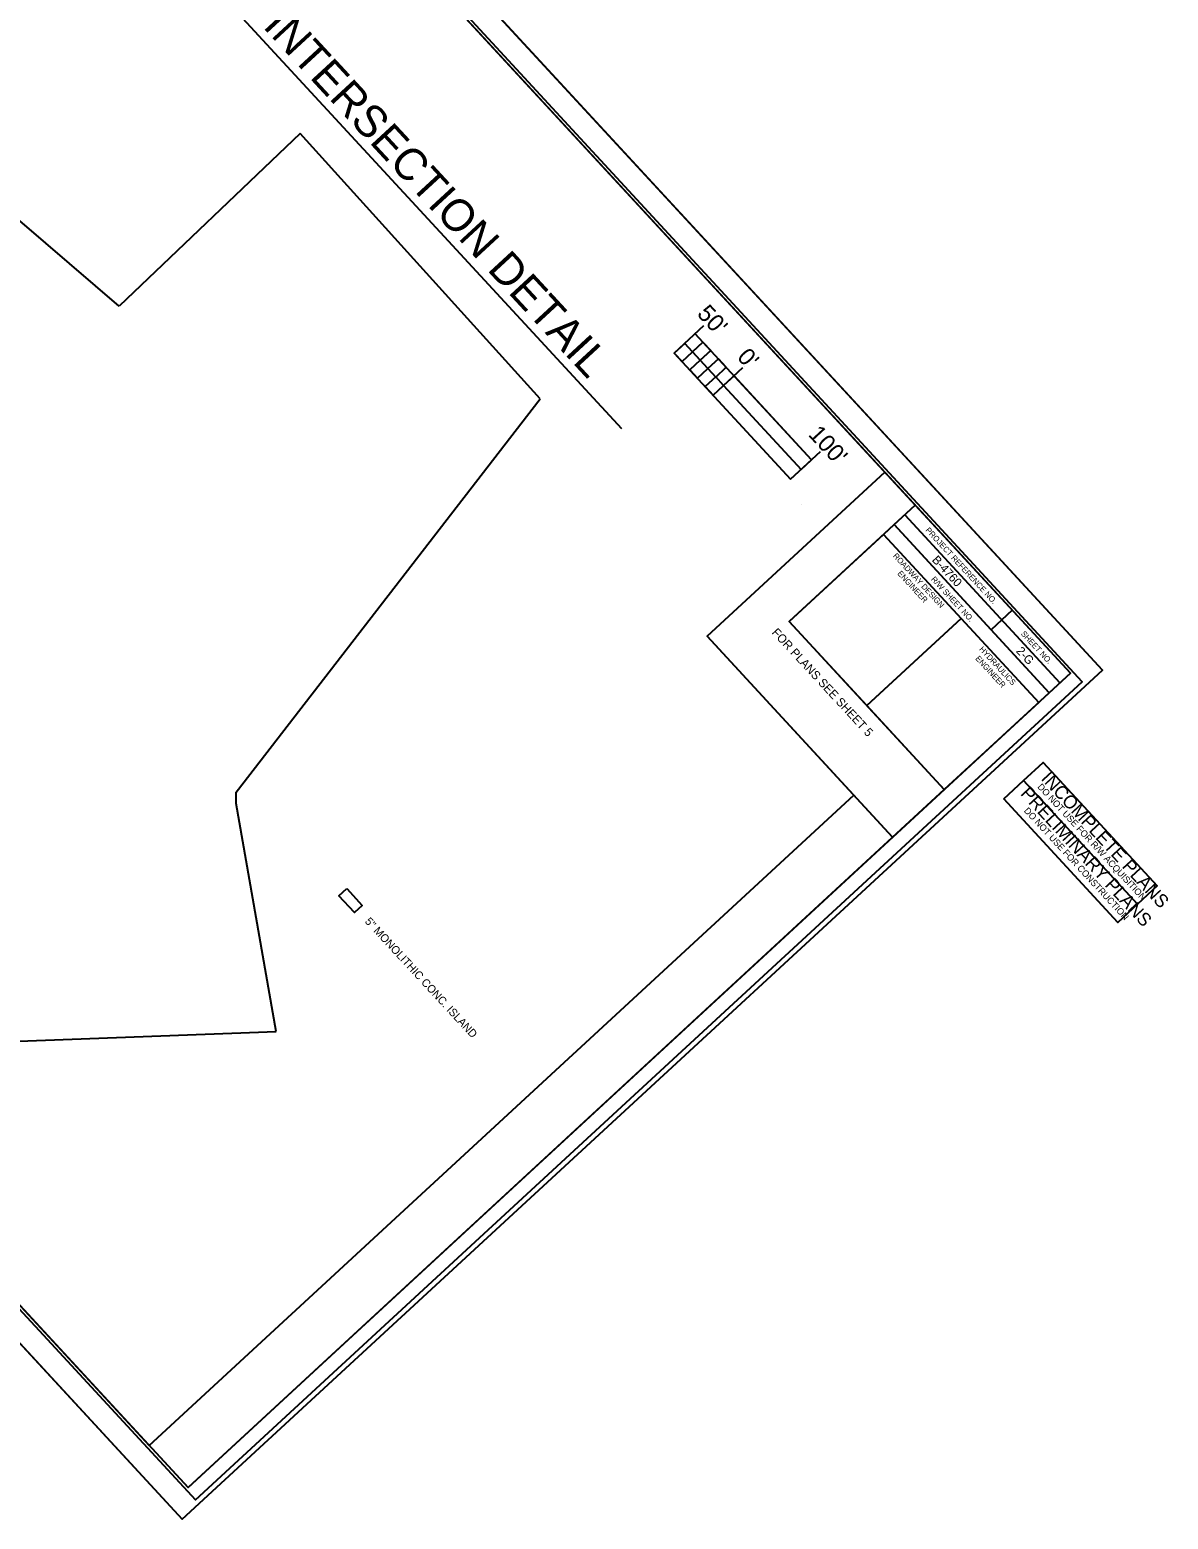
# Model space of a CAD drawing. Extents: x 1702855 to 1704859, y 793650 to 795630.
# Drawn here: x 1703864 to 1704859, y 793650 to 794953 of the extents above; entities that cross this region are included whole.
import ezdxf

# ---------------------------------------------------------------- set-up
doc = ezdxf.new("R2010")
doc.units = 0
for name, color, linetype in [('Prop Conc 5in Monolithic Surface Mount Island', 7, 'Continuous'), ('Prop Horizontal Alignment Curve and Spiral Data', 7, 'Continuous'), ('Prop Horizontal Alignment Station Label', 7, 'Continuous'), ('Prop PHM English Scale CELL', 7, 'Continuous'), ('Prop PHM Metric Scale CELL', 7, 'Continuous'), ('Sheet Clip Boundary CELL', 7, 'Continuous'), ('Sheet Cutting Line CELL', 7, 'Continuous'), ('Sheet Data Field CELL', 7, 'Continuous'), ('Sheet Layout Plan Border', 7, 'Continuous'), ('Sheet North Arrow Point CELL', 7, 'Continuous'), ('Sheet Plan CELL', 7, 'Continuous'), ('Sheet Plan Layout CELL', 7, 'Continuous'), ('Sheet Plot Border Inside CELL', 7, 'Continuous'), ('Sheet Plot Border Outside CELL', 7, 'Continuous'), ('Sheet Sticker Incomplete CELL', 7, 'Continuous'), ('Sheet Sticker Preliminary CELL', 7, 'Continuous')]:
    doc.layers.add(name, color=color, linetype=linetype)

msp = doc.modelspace()

# ---------------------------------------------------------------- linework, layer by layer
at = {"layer": 'Prop Conc 5in Monolithic Surface Mount Island'}
msp.add_lwpolyline([(1704140.9, 794201.9), (1704154.4, 794187.3), (1704147.5, 794180.9), (1704134, 794195.5)], close=True, dxfattribs=at)
at = {"layer": 'Prop Horizontal Alignment Curve and Spiral Data'}
msp.add_line((1703948.5, 795073), (1704381.1, 794604.3), dxfattribs=at)
at = {"layer": 'Prop PHM English Scale CELL'}
for p, q in [((1704452.9, 794694.1), (1704427.2, 794670.4)), ((1704547.3, 794577.1), (1704445.6, 794687.3)), ((1704427.2, 794670.4), (1704528.9, 794560.1)), ((1704486.8, 794657.4), (1704461.1, 794633.6)), ((1704488.3, 794658.7), (1704488.3, 794658.7)), ((1704554.7, 794583.9), (1704528.9, 794560.1)), ((1704556.1, 794585.2), (1704556.1, 794585.2)), ((1704528.9, 794560.1), (1704547.3, 794577.1))]:
    msp.add_line(p, q, dxfattribs=at)
at = {"layer": 'Prop PHM Metric Scale CELL'}
for points in [[(1704443.2, 794671.5), (1704436.4, 794678.8), (1704427.2, 794670.4), (1704434, 794663)], [(1704443.2, 794671.5), (1704436.4, 794678.8), (1704427.2, 794670.4), (1704434, 794663)], [(1704450, 794664.1), (1704443.2, 794671.5), (1704452.3, 794680), (1704459.1, 794672.6)], [(1704459.1, 794672.6), (1704452.3, 794680), (1704443.2, 794671.5), (1704449.9, 794664.1)], [(1704456.7, 794656.8), (1704449.9, 794664.1), (1704440.8, 794655.7), (1704447.5, 794648.3)], [(1704472.7, 794657.9), (1704465.9, 794665.3), (1704456.7, 794656.8), (1704463.5, 794649.4)], [(1704470.3, 794642.1), (1704463.5, 794649.5), (1704454.3, 794641), (1704461.1, 794633.6)], [(1704547.3, 794577.1), (1704479.5, 794650.6), (1704470.3, 794642.1), (1704538.1, 794568.6)]]:
    msp.add_lwpolyline(points, close=True, dxfattribs=at)
at = {"layer": 'Sheet Clip Boundary CELL'}
for p, q in [((1703941.8, 794711.4), (1703679.9, 794936.1)), ((1704100, 794862.5), (1703941.8, 794711.4)), ((1704310, 794630.4), (1704100, 794862.5))]:
    msp.add_line(p, q, dxfattribs=at)
msp.add_lwpolyline([(1703018.5, 794743.6), (1703968.1, 793714.8), (1704584.3, 794283.6), (1704455.9, 794422.7), (1704611.3, 794566.1), (1703790.1, 795455.8)], close=True, dxfattribs=at)
for points in [[(1704079, 794077), (1704044.1, 794276.3), (1704044, 794286.2), (1704310, 794630.4)], [(1703674.4, 794252.5), (1703678.6, 794245.3), (1703838.7, 794068), (1704079, 794077)]]:
    msp.add_lwpolyline(points, dxfattribs=at)
at = {"layer": 'Sheet Cutting Line CELL'}
for p, q in [((1704801.6, 794393), (1703659.7, 795630.1)), ((1702855.1, 794887.4), (1703997, 793650.3))]:
    msp.add_line(p, q, dxfattribs=at)
at = {"layer": 'Sheet Layout Plan Border'}
msp.add_lwpolyline([(1703018.5, 794743.6), (1703968.1, 793714.8), (1704584.3, 794283.6), (1704455.9, 794422.7), (1704611.3, 794566.1), (1703790.1, 795455.8)], close=True, dxfattribs=at)
at = {"layer": 'Sheet North Arrow Point CELL'}
msp.add_line((1704538.1, 794537.8), (1704538.1, 794537.8), dxfattribs=at)
at = {"layer": 'Sheet Plan CELL'}
for p, q in [((1704628.7, 794528.8), (1704764.3, 794381.8)), ((1704619.5, 794520.3), (1704610.3, 794511.8)), ((1704619.5, 794520.3), (1704755.2, 794373.3)), ((1704619.5, 794520.3), (1704755.2, 794373.3)), ((1704678.1, 794438.3), (1704595.5, 794362)), ((1704722.6, 794445.4), (1704704.3, 794428.4))]:
    msp.add_line(p, q, dxfattribs=at)
for points in [[(1704773.6, 794390.3), (1703756.2, 795492.5), (1702984.6, 794780.3), (1704002, 793678.1)], [(1702984.6, 794780.3), (1703756.1, 795492.5), (1704637.9, 794537.3), (1704527.6, 794435.5), (1704663.3, 794288.5), (1704002, 793678.1)], [(1704637.9, 794537.3), (1704773.6, 794390.3), (1704755.2, 794373.3), (1704619.5, 794520.3)], [(1704610.3, 794511.8), (1704678.1, 794438.3), (1704595.5, 794362), (1704527.6, 794435.5)], [(1704678.1, 794438.3), (1704746, 794364.8), (1704663.3, 794288.5), (1704595.5, 794362)]]:
    msp.add_lwpolyline(points, close=True, dxfattribs=at)
at = {"layer": 'Sheet Plan Layout CELL'}
for points in [[(1703756.1, 795492.5), (1702984.6, 794780.3), (1704002, 793678.1), (1704618.2, 794246.8), (1704455.9, 794422.7), (1704611.3, 794566.1)], [(1704455.9, 794422.7), (1704618.2, 794246.8), (1704773.6, 794390.3), (1704611.3, 794566.1)]]:
    msp.add_lwpolyline(points, close=True, dxfattribs=at)
at = {"layer": 'Sheet Plot Border Inside CELL'}
msp.add_lwpolyline([(1702878.6, 794891.4), (1704008.7, 793667.2), (1704783.9, 794382.8), (1703653.9, 795607)], close=True, dxfattribs=at)
at = {"layer": 'Sheet Plot Border Outside CELL'}
msp.add_lwpolyline([(1702855.1, 794887.4), (1703997, 793650.3), (1704801.6, 794393), (1703659.7, 795630.1)], close=True, dxfattribs=at)
at = {"layer": 'Sheet Sticker Incomplete CELL'}
msp.add_lwpolyline([(1704732.6, 794296.4), (1704749.9, 794312.3), (1704849.6, 794204.3), (1704832.3, 794188.4)], close=True, dxfattribs=at)
at = {"layer": 'Sheet Sticker Preliminary CELL'}
msp.add_lwpolyline([(1704715.3, 794280.4), (1704732.6, 794296.4), (1704832.3, 794188.4), (1704815, 794172.4)], close=True, dxfattribs=at)

# ---------------------------------------------------------------- texts
at = {"layer": 'Prop Horizontal Alignment Curve and Spiral Data'}
msp.add_text('-LOOPC- INTERSECTION DETAIL', height=28, rotation=312.7091, dxfattribs=at).set_placement((1703953.9, 795078))
at = {"layer": 'Prop Horizontal Alignment Station Label'}
msp.add_text('FOR PLANS SEE SHEET 5', height=7.5, rotation=312.7091, dxfattribs=at).set_placement((1704512, 794425.5))
at = {"layer": 'Prop PHM English Scale CELL'}
for s, p in [("50'", (1704446.4, 794704.1)), (" 0'", (1704477.6, 794670.3)), ("100'", (1704543.7, 794598.7))]:
    msp.add_text(s, height=15, rotation=312.7091, dxfattribs=at).set_placement(p)
at = {"layer": 'Sheet Data Field CELL'}
for s, p in [('B-4760', (1704652.1, 794489)), ('2-G', (1704725.7, 794409.3))]:
    msp.add_text(s, height=7.5, rotation=312.7091, dxfattribs=at).set_placement(p)
at = {"layer": 'Sheet Plan CELL'}
for s, height, p in [('PROJECT REFERENCE NO.', 5, (1704646.5, 794515.1)), ('ROADWAY DESIGN', 5, (1704618.1, 794492.6)), ('ENGINEER', 5, (1704622, 794477.2)), ('R/W SHEET NO.', 5, (1704651.4, 794472.2)), ('SHEET NO.', 5, (1704730, 794424.5)), ('HYDRAULICS', 5, (1704693.5, 794411)), ('ENGINEER', 5, (1704690.2, 794402.8)), ('5" MONOLITHIC CONC. ISLAND', 7, (1704156.2, 794172.8))]:
    msp.add_text(s, height=height, rotation=312.7091, dxfattribs=at).set_placement(p)
at = {"layer": 'Sheet Sticker Incomplete CELL'}
for s, height, p in [('INCOMPLETE PLANS', 11.52, (1704747.3, 794297.7)), ('DO NOT USE FOR R/W ACQUISITION', 5.76, (1704744.4, 794290.6))]:
    msp.add_text(s, height=height, rotation=312.7091, dxfattribs=at).set_placement(p)
at = {"layer": 'Sheet Sticker Preliminary CELL'}
for s, height, p in [('PRELIMINARY PLANS', 11.52, (1704729.4, 794284.6)), ('DO NOT USE FOR CONSTRUCTION', 5.76, (1704732.6, 794269.7))]:
    msp.add_text(s, height=height, rotation=312.7091, dxfattribs=at).set_placement(p)

doc.saveas('drawing.dxf')
